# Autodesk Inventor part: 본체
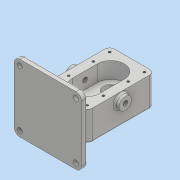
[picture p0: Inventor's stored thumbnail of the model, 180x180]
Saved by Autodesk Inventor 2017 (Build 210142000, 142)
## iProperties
Part Number: 본체
Material: 일반
Document SubType Name: Modeling
Designer: MRC
Density: 1 g/cm^3
Appearance: 기본값
Mass: 569.071 g
Surface Area: 871.376 cm^2
Volume: 569.071 cm^3
Author: MRC
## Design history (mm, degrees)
sketch "스케치1"
  geometry: L1 (40, -60)-(-40, -60); L2 (-40, -60)-(-40, 60); L3 (-40, 60)-(40, 60); L4 (40, 60)-(40, -60); L5 (40, -60)-(-40, 60); L6 (-40, -60)-(40, 60); 1 further point
  constraints: 12 end point, 2 midpoint, 2 parallel, 1 horizontal, 1 perpendicular
  dimensions: "d0" = 80 distance of L2.end L3.end; "d1" = 120 distance of L1.end L2.end
extrude "돌출1" new body sketch "스케치1" distance "d2" = 14; taper "d4" = 0 deg; dims "d3" = 39, "d5" = 0
fillet "모깎기1" dims "d6" = 9
sketch "스케치2"
  geometry: L1 (0, -22)-(0, 22); L2 (-24, -22)-(-24, 22); L3 (24, 22)-(24, -22); A1 r 24 centre (0, -22) between (-24, -22) and (24, -22); A2 r 24 centre (0, 22) between (24, 22) and (-24, 22); 1 further point
  constraints: 8 end point, 4 point on circle, 4 tangent, 2 centre point, 1 midpoint, 1 parallel, 1 vertical
  dimensions: "d7" = 24 radius of A2; "d8" = 44 distance of L3.start L3.end
extrude "돌출2" cut sketch "스케치2" distance "d9" = 29; taper "d10" = 0 deg
sketch "스케치4"
  geometry: C1 r 19 at (0, 22); A1 r 24 centre (0, 22) between (24, 22) and (-24, 22) reference; 1 further point
  constraints: 1 centre point, 1 concentric
  dimensions: "d11" = 38 diameter of C1
extrude "돌출3" join sketch "스케치4" distance "d12" = 17; taper "d13" = 0 deg
hole "구멍1" diameter "d16" = 17; stored, may be unused: countersink angle "d20" = 90 deg, drill point angle "d22" = 118 deg; dims "d14" = 10, "d15" = 10, "d17" = 6, "d18" = 28, "d19" = 7.3, "d21" = 8
sketch "스케치5"
  geometry: C1 r 8.5 at (0, 22) reference; C2 r 12.5 at (0, 22); C3 r 12.5 at (0, -22); A1 r 24 centre (0, -22) between (-24, -22) and (24, -22) reference; A2 r 24 centre (0, 22) between (24, 22) and (-24, 22) reference; 1 further point
  constraints: 2 centre point, 2 coincident
  dimensions: "d23" = 25 diameter of C2; "d24" = 25 diameter of C3
extrude "돌출4" cut sketch "스케치5" distance "d25" = 15; taper "d26" = 0 deg
fillet "모깎기2" dims "d27" = 0.5
chamfer "모따기1" distance "d28" = 0.7; stored, may be unused: second distance "d29" = 2, angle "d30" = 30 deg
fillet "모깎기3" dims "d31" = 3
sketch "스케치6"
  geometry: C1 r 11 at (14, 51); 1 further point
  constraints: 1 centre point, 1 coincident
  dimensions: "d32" = 22 diameter of C1
extrude "돌출5" join sketch "스케치6" distance "d33" = 8; taper "d34" = 0 deg
hole "구멍2" diameter "d37" = 8.376; stored, may be unused: countersink angle "d41" = 90 deg, drill point angle "d43" = 118 deg; dims "d35" = 10, "d36" = 10, "d38" = 20, "d39" = 28, "d40" = 7.3, "d42" = 27.3
fillet "모깎기5" dims "d45" = 3
sketch "스케치7"
  geometry: A1 r 9 centre (31, -51) between (31, -60) and (40, -51) reference; A2 r 9 centre (31, 51) between (40, 51) and (31, 60) reference; A3 r 9 centre (-31, 51) between (-31, 60) and (-40, 51) reference; A4 r 9 centre (-31, -51) between (-40, -51) and (-31, -60) reference; 9 further points
  constraints: 4 coincident, 4 vertical alignment, 2 horizontal alignment
  dimensions: "d46" = 29 distance of point (-31, 22) point (-31, 51); "d47" = 29 distance of point (31, -22) point (31, -51)
hole "구멍3" sketch "스케치7" at (-31, 51), (31, 51), (31, -51), (-31, -51), (-31, 22), (-31, -22), (31, 22), (31, -22) diameter "d48" = 4.134; stored, may be unused: countersink angle "d52" = 90 deg, drill point angle "d54" = 118 deg; dims "d49" = 10, "d50" = 28, "d51" = 7.3, "d53" = 12
sketch "스케치8"
  geometry: L1 (-80, 64)-(-90, 64); L2 (-90, 64)-(-90, -56); L3 (-90, -56)-(-80, -56); L4 (-80, -56)-(-80, 64); L5 (60, -36)-(60, 14) reference; L6 (3, -56)-(41, -56) reference; L7 (-80, -39)-(-60, -27.453); L8 (-80, 14)-(-60, 2.453); L9 (-60, -36)-(-60, 14) reference; 1 further point
  constraints: 12 end point, 4 point on line, 2 parallel, 1 horizontal, 1 perpendicular
  dimensions: "d55" = 120 distance of L1.end L2.end; "d56" = 150 distance between parallel lines of L5 L2; "d57" = 10 distance of L2.end L3.end; "d58" = 0 distance between parallel lines of L3 L6; "d59" = 53 distance of L8.start L7.start; "d60" = 17 distance from line of L3 L7.start; "d61" = 60 deg angle of L4 L7; "d62" = 60 deg angle of L4 L8
extrude "돌출6" join sketch "스케치8" stored distance "d63" = 120; taper "d64" = 0 deg
extrude "돌출7" join sketch "스케치8" stored distance "d65" = 48; taper "d66" = 0 deg
fillet "모깎기6" dims "d67" = 10
fillet "모깎기7" dims "d68" = 3
fillet "모깎기8" dims "d69" = 3
sketch "스케치9"
  geometry: A1 r 7 centre (100, -7) between (107, -7) and (100, 0) reference; A2 r 7 centre (0, -7) between (0, 0) and (-7, -7) reference; A3 r 7 centre (0, -107) between (-7, -107) and (0, -114) reference; A4 r 7 centre (100, -107) between (100, -114) and (107, -107) reference; 5 further points
  constraints: 4 coincident
hole "구멍4" sketch "스케치9" at (0, -7), (100, -7), (100, -107), (0, -107) diameter "d70" = 9; stored, may be unused: countersink angle "d74" = 90 deg, drill point angle "d76" = 118 deg; dims "d71" = 10, "d72" = 28, "d73" = 7.3, "d75" = 9
chamfer "모따기2" distance "d77" = 1; stored, may be unused: second distance "d78" = 2, angle "d79" = 30 deg
sketch "스케치10"
  geometry: L1 (0, -117)-(100, -117) reference; L2 (-10, -7)-(-10, -107) reference; 2 further points
  constraints: 1 other
  dimensions: "d80" = 10 distance from line of point (50, -107) L1; "d81" = 60 distance from line of point (50, -107) L2
feature "엠보싱1" sketch "스케치10" dims "d0" = 80, "d1" = 120, "d82" = 0.5, "d83" = 0
fillet "모깎기9" dims "d84" = 3
node "솔리드1"
mirror "미러1"
